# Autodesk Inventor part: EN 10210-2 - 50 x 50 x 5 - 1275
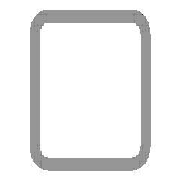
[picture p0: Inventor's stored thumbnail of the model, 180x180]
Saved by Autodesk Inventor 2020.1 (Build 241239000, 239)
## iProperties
IsCustomPart: 1
Created: 2019-10
Part Number: EN 10210-2 - 50 x 50 x 5 - 1275
Material: Stahl, weich
Description: Rohrleitung
Document SubType Name: Modeling
Standard: DIN
Designer: lutzd
Standard Revision: 2006-07
Standards Organization: DIN
Language: de-DE
Size Designation: 50 x 50 x 5
Categories: <MemberInstance><Categories><Category DisplayName="Profile" InternalName="089c4875-fa83-4c05-b084-43b9cc11f5ed" Mnemonic="GRDR"><CategoryParameter DisplayName="
Stock Number: 50 x 50 x 5
Mass: 8739.39 g
Surface Area: 4333.85 cm^2
Volume: 1113.3 cm^3
Density: 7.85 g/cm^3
Appearance: Halbpoliert
_CCFamilyMember: 16
_CCFamilyDisplayName: DIN EN 10210-2 (USAS B17.1 quadratisch) - Rohrleitung — In Klammern angegebene Größen wurden aufgehoben
_FrameMemberDoc: Frame Member File
_Version: 15.0.0
_GetPNFromCC: 1
G_L: 1275,000 mm
G_W: 50,000 mm
G_H: 50,000 mm
Dimensions: 50x50x1275 mm
Mass: 8,739 kg
DocNumber: ADSK-014147
Folder: .
+807B5F9E-1F44-437F-901D-40C91D3C5DFB+SCHNITTDETAIL1: Schnittwinkel 90,00 grd
+954D4CEF-0715-4280-AE01-AF74F0C35052+SCHNITTDETAIL2: Schnittwinkel 90,00 grd
Title: Profil-Bauteil
Author: lutzd
Revision Number: -
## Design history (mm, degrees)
node "Startebene"
node "Endebene"
sketch "Skizze"
  geometry: L1 (-25, -17.5)-(-25, 17.5); L2 (-17.5, 25)-(17.5, 25); L3 (25, 17.5)-(25, -17.5); L4 (17.5, -25)-(-17.5, -25); L5 (-15, 20)-(15, 20); L6 (20, 15)-(20, -15); L7 (15, -20)-(-15, -20); L8 (-20, -15)-(-20, 15); L9 (0, 37.175)-(0, -37.175) reference; L10 (-37.175, 0)-(37.175, 0) reference; A1 r 7.5 centre (-17.5, -17.5) between (-25, -17.5) and (-17.5, -25); A2 r 7.5 centre (-17.5, 17.5) between (-17.5, 25) and (-25, 17.5); A3 r 7.5 centre (17.5, 17.5) between (25, 17.5) and (17.5, 25); A4 r 7.5 centre (17.5, -17.5) between (17.5, -25) and (25, -17.5); A5 r 5 centre (-15, -15) between (-20, -15) and (-15, -20); A6 r 5 centre (-15, 15) between (-15, 20) and (-20, 15); A7 r 5 centre (15, 15) between (20, 15) and (15, 20); A8 r 5 centre (15, -15) between (15, -20) and (20, -15)
  constraints: 16 end point, 16 point on circle, 16 tangent, 8 centre point, 6 equal radius, 4 parallel, 2 perpendicular, 2 other
  dimensions: "d7" = 7.5 radius of A1 (= G_IR); "d10" = 50 distance between parallel lines of L2 L4 (= G_H); "d11" = 50 distance between parallel lines of L1 L3 (= G_W); "d12" = 5 distance between parallel lines of L3 L6 (= G_T); "d15" = 25 distance between parallel lines of L2 L10 (= 0.5 x d10); "d16" = 25 distance between parallel lines of L9 L3 (= 0.5 x d11); "d19" = 5 radius of A5 (= G_T); "d20" = 5 distance between parallel lines of L4 L7 (= G_T)
extrude "Körper" new body sketch "Skizze" stored distance "d3" = 1275 (= G_L); taper "d4" = 0 deg
node "Driven Length"
  sketch "Sketch3"
    geometry: L1 (0, 0)-(10, 0) reference
    constraints: 2 end point, 1 horizontal
  workplane "Work Plane3"
  sketch "Sketch4"
    geometry: L1 (-2, 50)-(12, 50) reference; L2 (-2, 1325)-(12, 1325) reference
    dimensions: "d18" = 1275 distance between parallel lines of L1 L2 (derived)
workplane "Arbeitsebene4"
feature "Trennen1"
workplane "Arbeitsebene5"
feature "Trennen2"
body "Solid1"
other parameters: "G_W" = 50 [user parameter; used in 1 equation term], "G_H" = 50 [user parameter; used in 1 equation term], "G_T" = 5 [user parameter; used in 3 equation terms], "G_IR" = 7.5 [user parameter; used in 1 equation term], "G_L" = 1275 (= d18) [user parameter; used in 1 equation term], "d14" = 1325 (= G_OFFSET_END + B_L), "B_L" = 1375 [user parameter; used in 1 equation term], "d17" = 90 deg
